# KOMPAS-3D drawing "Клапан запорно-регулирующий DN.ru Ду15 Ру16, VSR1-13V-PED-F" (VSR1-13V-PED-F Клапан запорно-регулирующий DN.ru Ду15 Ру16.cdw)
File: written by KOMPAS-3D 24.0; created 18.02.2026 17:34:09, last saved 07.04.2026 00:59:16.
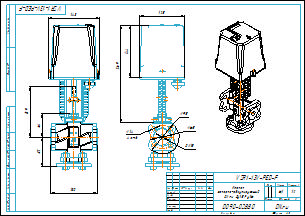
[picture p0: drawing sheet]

Document properties: Автор: R2D2; Форматы листов документа: A3; Полное имя файла: VSR1-13V-PED-F Клапан запорно-регулирующий DN.ru Ду15 Ру16.m3d; Масса: 6.1; Наименование: Клапан запорно-регулирующий DN.ru Ду15 Ру16; Количество листов документа: 1; Примечание: D090-02880

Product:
- Part/product: Клапан запорно-регулирующий DN.ru Ду15 Ру16  | designation VSR1-13V-PED-F
    Масса: 6.1
    Раздел спецификации: Прочие изделия
    Форматы листов документа: A3
    Примечание: D090-02880

Views: Вид 1, Спереди
Referenced files in E:\Работа\Зайцев\Солянка\VSR1-13V-PED-F Клапан запорно-регулирующий DN.ru\DN15\DN15 Kv0.16\: VSR1-13V-PED-F Клапан запорно-регулирующий DN.ru Ду15 Ру16.m3d
Referenced files in E:\Работа\Зайцев\Для компаса\: чертеж DN.ru А3.cdt
Referenced files in E:\Работа\Зайцев\Солянка\VSR1-13V-PED-F Клапан запорно-регулирующий DN.ru\DN15\DN15 Kv0.2\: VSR1-13V-PED-F Клапан запорно-регулирующий DN.ru Ду15 Ру16.m3d
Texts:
  Линейный размер
  VSR1-13V-PED-F
  чертеж DN.ru А3.cdt
  Клапан
  запорно-регулирующий
  DN.ru Ду15 Ру16
  Клапан запорно-регулирующий DN.ru Ду15 Ру16
  VSR1-13V-PED-F Клапан запорно-регулирующий DN.ru Ду15 Ру16
Dimensions and other numbers on the sheet: 0; 3; 2; 4; 130; 82; 143; 64; 139; 1:2; 1; 6,1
